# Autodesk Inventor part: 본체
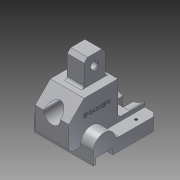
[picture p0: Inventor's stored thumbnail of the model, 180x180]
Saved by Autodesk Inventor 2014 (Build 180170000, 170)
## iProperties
Created: 2016-11
Part Number: 본체
Material: 알루미늄 6061
Document SubType Name: Modeling
Designer: USER
Density: 2.71 g/cm^3
Appearance: 알루미늄 - 평지
Mass: 462.907 g
Surface Area: 317.29 cm^2
Volume: 170.814 cm^3
Author: USER
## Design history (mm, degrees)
sketch "스케치1"
  geometry: L1 (0, 0)-(18, 18); L2 (18, 18)-(58, 18); L3 (58, 18)-(58, -22); L4 (58, -22)-(90, -22); L5 (90, -22)-(90, -42); L6 (90, -42)-(27, -42); L7 (27, -42)-(27, -30); L8 (27, -30)-(0, -30); L9 (0, -30)-(0, 0)
  constraints: 18 end point, 6 perpendicular, 1 horizontal, 1 parallel
  dimensions: "d0" = 45 deg angle of L1 L2; "d1" = 30 distance from line of L8 L1.start; "d2" = 58 distance between parallel lines of L3 L9; "d3" = 90 distance between parallel lines of L5 L9; "d4" = 48 distance between parallel lines of L8 L2; "d5" = 60 distance between parallel lines of L6 L2; "d6" = 20 distance of L4.end L5.end; "d7" = 63 distance of L5.end L6.end
extrude "돌출1" new body sketch "스케치1" stored distance "d8" = 40; taper "d9" = 0 deg
sketch "스케치2"
  geometry: L1 (30, 0)-(30, 27) reference; L2 (30, 27)-(42, 27) reference; L3 (42, 27)-(42, 90) reference; L4 (42, 90)-(22, 90) reference; L5 (-18, 58)-(-18, 18) reference; L6 (27, 14)-(42, 14); L7 (42, 14)-(42, 17); L8 (42, 17)-(35, 17); L9 (35, 17)-(35, 37); L10 (35, 37)-(42, 37); L11 (27, 40)-(27, 90); A1 r 13 centre (27, 27) between (27, 40) and (27, 14)
  constraints: 12 end point, 6 perpendicular, 2 point on circle, 2 point on line, 1 centre point, 1 tangent
  dimensions: "d11" = 15 distance from line of A1.centre L3; "d12" = 63 distance from line of L4 A1.centre; "d13" = 20 distance of L8.end L9.end; "d14" = 3 distance of L6.end L7.end; "d15" = 7 distance of L7.end L8.end; "d16" = 7 distance between parallel lines of L3 L9; "d17" = 13 radius of A1; "d18" = 50 distance of L11.start L11.end
extrude "돌출2" join sketch "스케치2" distance "d19" = 15; taper "d20" = 0 deg
sketch "스케치3"
  geometry: L1 (-30, 27)-(-35, 27) reference; L2 (-42, 17)-(-35, 17) reference; L3 (-30, 14)-(-42, 14) reference; L4 (-30, 14)-(-30, 27) reference; L5 (-35, 27)-(-30, 27); L6 (-30, 14)-(-42, 14); L7 (-35, 27)-(-35, 17); L8 (-35, 17)-(-42, 17); L9 (-42, 17)-(-42, 14); L10 (-30, 27)-(-30, 14); 1 further point
  constraints: 12 end point, 3 collinear, 3 perpendicular
extrude "돌출3" join sketch "스케치3" stored distance "d21" = 15; taper "d22" = 0 deg
sketch "스케치4"
  geometry: L1 (35, 17)-(42, 17); L2 (42, 17)-(42, 37); L3 (42, 37)-(35, 37); L4 (35, 37)-(35, 17); 1 further point
  constraints: 8 end point, 2 parallel, 1 horizontal, 1 perpendicular
extrude "돌출4" cut sketch "스케치4" stored distance "d23" = 0; taper "d24" = 0 deg
sketch "스케치5"
  geometry: L1 (58, 18)-(18, 18) reference; L2 (28, 18)-(28, 48); L3 (28, 48)-(53, 48); L4 (53, 48)-(53, 18); L5 (58, -22)-(58, 18) reference; L6 (37, -42)-(90, -42) reference; 1 further point
  constraints: 6 end point, 3 perpendicular, 2 point on line
  dimensions: "d25" = 5 distance between parallel lines of L5 L4; "d26" = 25 distance of L2.end L3.end; "d27" = 90 distance between parallel lines of L6 L3
extrude "돌출5" join sketch "스케치5" stored distance "d28" = 20; taper "d29" = 0 deg
sketch "스케치6"
  geometry: L1 (-48, 28)-(-18, 28) reference; L2 (42, 37)-(42, 90) reference; C1 r 4 at (-35, 40.5); 1 further point
  constraints: 1 centre point
  dimensions: "d30" = 8 diameter of C1; "d31" = 12.5 distance from line of L1 C1.centre; "d32" = 77 distance from line of L2 C1.centre
extrude "돌출6" cut sketch "스케치6" distance "d33" = 20; taper "d34" = 0 deg
sketch "스케치7"
  geometry: L1 (0, 0)-(40, 0) reference; L2 (55, 60)-(-15, 60) reference; C1 r 14.5 at (20, 18); 2 further points
  constraints: 1 centre point, 1 midpoint, 1 vertical alignment
  dimensions: "d35" = 29 diameter of C1; "d36" = 42 distance from line of L2 C1.centre
extrude "돌출7" cut sketch "스케치7" distance "d37" = 7; taper "d38" = 0 deg
sketch "스케치8"
  geometry: C1 r 14.5 at (0, 0) reference; C2 r 10 at (0, 0)
  constraints: 1 centre point, 1 coincident
  dimensions: "d39" = 20 diameter of C2
extrude "돌출8" cut sketch "스케치8" stored distance "d40" = 7; taper "d41" = 0 deg
chamfer "모따기1" distance "d42" = 1; stored, may be unused: second distance "d43" = 2, angle "d44" = 45 deg
sketch "스케치9"
  geometry: C1 r 29 at (20, -22); 1 further point
  constraints: 1 centre point, 1 coincident
  dimensions: "d45" = 58 diameter of C1
extrude "돌출9" cut sketch "스케치9" distance "d46" = 18; taper "d47" = 0 deg
sketch "스케치10"
  geometry: L1 (38.894, 14)-(1.106, 14) reference; L2 (14, 14)-(26, 14); L3 (26, 14)-(26, 45.797); L4 (26, 45.797)-(14, 45.797); L5 (14, 45.797)-(14, 14); 4 further points
  constraints: 8 end point, 3 midpoint, 2 coincident, 2 parallel, 1 horizontal, 1 perpendicular
  dimensions: "d48" = 31.79699 distance of L4.end L2.start; "d49" = 12 distance of L3.end L4.end
extrude "돌출10" cut sketch "스케치10" distance "d50" = 30; taper "d51" = 0 deg
sketch "스케치11"
  geometry: L1 (15, 0)-(0, 0) reference; L2 (45, -90)-(25, -90) reference; L3 (55, 0)-(70, 0) reference; L4 (53.894, -18)-(16.106, -18) reference; L5 (35, -18)-(35, 7.709); 3 further points
  constraints: 2 end point, 1 midpoint, 1 perpendicular
  dimensions: "d52" = 18 distance from line of L1 point (7.5, -18); "d53" = 18 distance from line of L3 point (62.5, -18); "d54" = 55 distance of point (62.5, -18) point (7.5, -18); "d55" = 27.5 distance from line of L5 point (7.5, -18)
hole "구멍1" sketch "스케치11" at (7.5, -18), (62.5, -18) diameter "d56" = 3.242; stored, may be unused: countersink angle "d60" = 90 deg, drill point angle "d62" = 118 deg; dims "d57" = 6, "d58" = 4, "d59" = 2, "d61" = 8
chamfer "모따기2" distance "d63" = 4; stored, may be unused: second distance "d64" = 2, angle "d65" = 45 deg
chamfer "모따기3" distance "d66" = 1; stored, may be unused: second distance "d67" = 2, angle "d68" = 45 deg
chamfer "모따기4" distance "d69" = 5; stored, may be unused: second distance "d70" = 2, angle "d71" = 45 deg
fillet "모깎기1" dims "d72" = 5
fillet "모깎기2" dims "d73" = 3
sketch "스케치12"
  geometry: L1 (19, 58)-(-18, 58) reference; L2 (-18, 58)-(-18, 18) reference; 1 further point
  constraints: 1 other
  dimensions: "d74" = 25 distance from line of L1 point (0, 33); "d75" = 18 distance from line of L2 point (0, 33)
feature "엠보싱1" sketch "스케치12" dims "d0" = 45 deg, "d1" = 30, "d2" = 58, "d3" = 90, "d4" = 48, "d5" = 60, "d6" = 20, "d7" = 63, "d11" = 15, "d12" = 63, "d13" = 20, "d14" = 3, "d15" = 7, "d16" = 7, "d17" = 13, "d18" = 50, "d76" = 0.5, "d77" = 0
chamfer "모따기5" distance "d78" = 4; stored, may be unused: second distance "d79" = 2, angle "d80" = 45 deg
node "솔리드1"
mirror "대칭1"
other parameters: "d10" = 26
